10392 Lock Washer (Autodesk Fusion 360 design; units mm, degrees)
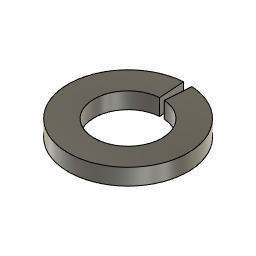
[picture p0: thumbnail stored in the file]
sketch "Main Profile" plane through (0, 0, 0) normal (0, 0, 1) x axis (1, 0, 0)
  line L1 (0, 8.7313) -> (0, 0)
  line L2 (0.3461, 4.9489) -> (0, 0)
  line L3 (-0.3461, 4.9489) -> (0, 0)
  line L4 (0.6091, 8.71) -> (0.3461, 4.9489)
  line L5 (-0.6091, 8.71) -> (-0.3461, 4.9489)
  circle C1 centre (0, 0) radius 8.7313
  circle C2 centre (0, 0) radius 4.9609
  point P1 (0, 0)
  point P2 (0, 0)
  point P4 (0, 0)
  point P5 (0, 8.7313)
  point P3 (0, 0)
  point P6 (0, 0)
  point P7 (0.3461, 4.9489)
  point P8 (0, 0)
  point P9 (-0.3461, 4.9489)
  point P10 (0.6091, 8.71)
  point P11 (-0.6091, 8.71)
  coincident P1 P2
  concentric C1 C2
  coincident P1 P4
  coincident C1 P5
  vertical L1
  coincident P3 P6
  coincident C2 P7
  coincident P2 P8
  coincident C2 P9
  coincident C1 P10
  parallel L2 L4
  coincident C1 P11
  parallel L3 L5
  symmetric L1 L4 L5
  dimension "d1" diameter C1 = 17.4625 (= "( 11 / 16 ) * 1 in")
  dimension "d2" diameter C2 = 9.9219 (= "( 25 / 64 ) * 1 in")
  dimension "d3" angle L4 L5 = 8
extrude "Extrude1" new body sketch "Main Profile" profile of C1 C2 L4 L5 along normal blind 2.3813 (= "( 3 / 32 ) * 1 in") bodies "10392 Lock Washer"
named bodies: "10392 Lock Washer"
